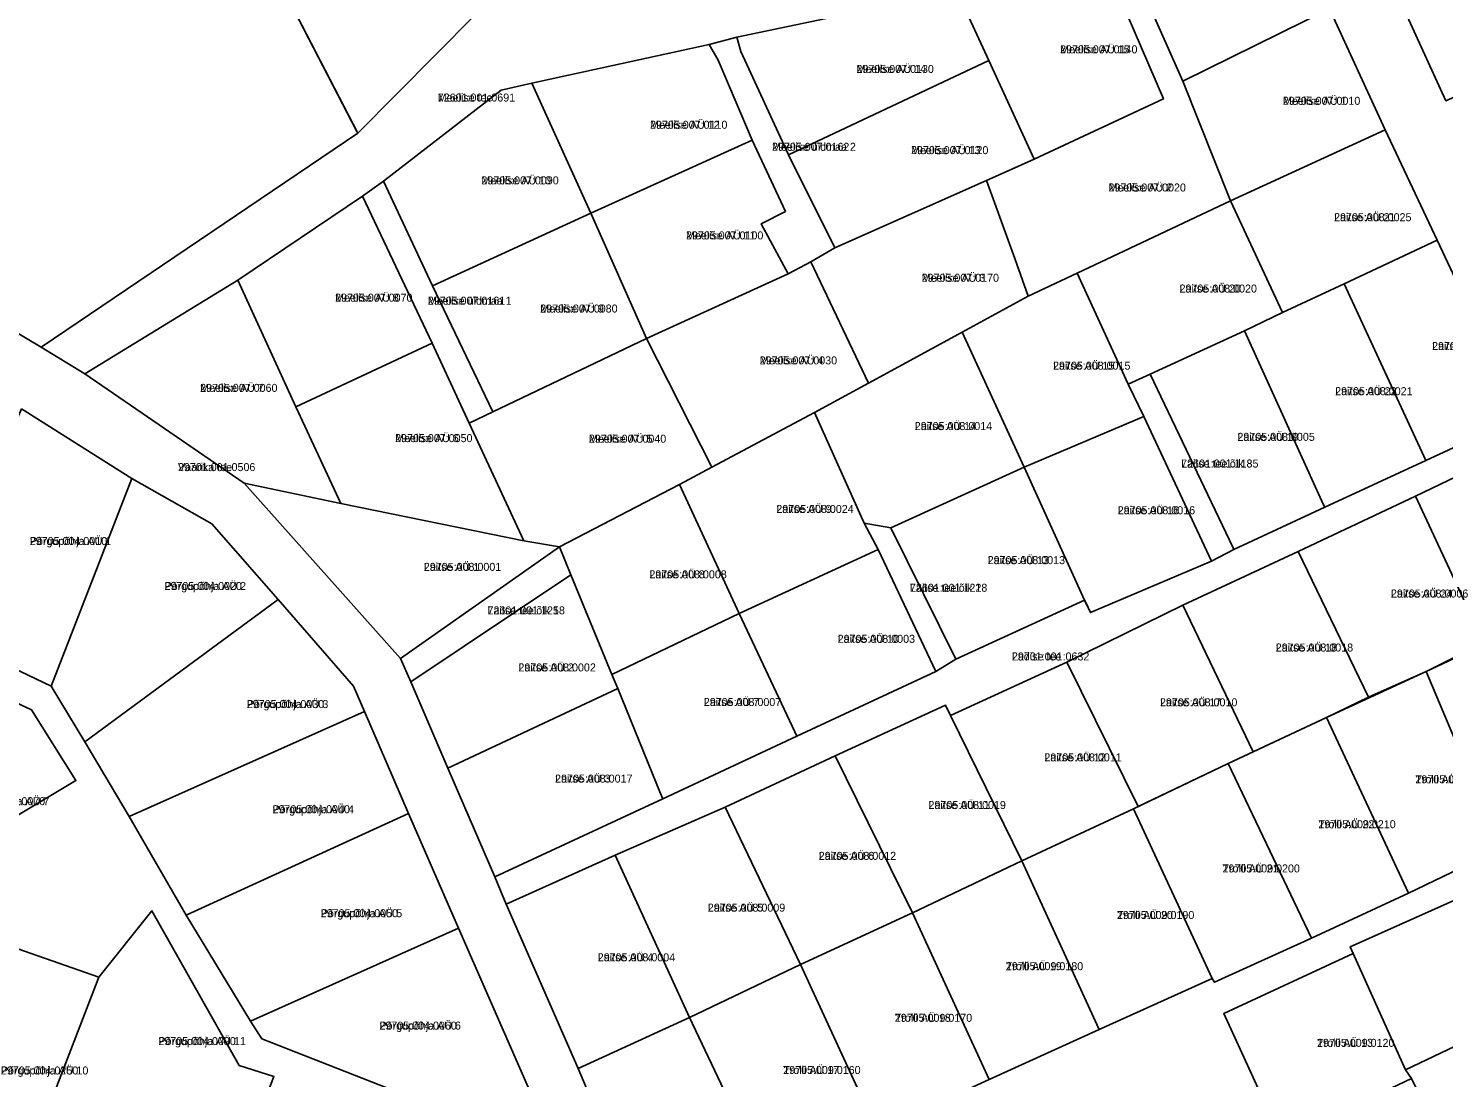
# Model space of a CAD drawing. Extents: x 504287 to 537970, y 6539941 to 6586214.
# Drawn here: x 519008.5 to 519273.8, y 6563004.5 to 6563201.2 of the extents above; entities that cross this region are included whole.
import ezdxf

# ---------------------------------------------------------------- set-up
doc = ezdxf.new("R2010")
doc.units = 0
for name, color, linetype in [('L_AADRESS', 7, 'Continuous'), ('PIIR', 7, 'Continuous'), ('TUNNUS', 7, 'Continuous')]:
    doc.layers.add(name, color=color, linetype=linetype)

msp = doc.modelspace()

# ---------------------------------------------------------------- linework, layer by layer
at = {"layer": 'PIIR'}
for points in [[(519053.34, 6563236.21), (519046.68, 6563227.13), (519070.28, 6563181.56), (519010.92, 6563141.43), (518931.33, 6563188.8), (519001.41, 6563278.34)], [(519236.2, 6563238.48), (519243.47, 6563223.81), (519238.26, 6563225.44), (519213.24, 6563217.67), (519209.13, 6563216.28), (519182.57, 6563208.19), (519141.33, 6563199.52), (519136.15, 6563198.16), (519102.94, 6563190.91), (519097.15, 6563189.57), (519075.1, 6563172.56), (519071.2, 6563169.74), (519047.83, 6563153.98), (519019.15, 6563136.44), (519010.92, 6563141.43), (519070.28, 6563181.56), (519092.24, 6563203.65), (519125.45, 6563208.08), (519151.08, 6563213.3), (519170.59, 6563217.51), (519190.06, 6563221.91), (519216.47, 6563228.93)], [(519070.28, 6563181.56), (519070.12, 6563181.87), (519046.68, 6563227.13), (519053.32, 6563236.18), (519074.71, 6563218.2), (519092.24, 6563203.65)], [(519293.15, 6563234.92), (519298.22, 6563198.28), (519274.24, 6563187.6), (519254.72, 6563230.35)], [(519213.24, 6563217.67), (519238.26, 6563225.44), (519243.47, 6563223.81), (519252.43, 6563204.86), (519224.92, 6563191.31)], [(519195.93, 6563150.95), (519193.44, 6563158.03), (519188.13, 6563172.69), (519197.09, 6563176.65), (519221.29, 6563187.94), (519209.13, 6563216.28), (519213.24, 6563217.67), (519224.92, 6563191.31), (519233.88, 6563168.84), (519205.14, 6563155.29)], [(519188.58, 6563195.18), (519182.57, 6563208.19), (519209.13, 6563216.28), (519221.29, 6563187.94), (519197.09, 6563176.65)], [(519142.12, 6563196.85), (519141.33, 6563199.52), (519182.57, 6563208.19), (519188.58, 6563195.18), (519151.01, 6563177.45)], [(519224.92, 6563191.31), (519252.43, 6563204.86), (519262.87, 6563182.15), (519233.88, 6563168.84)], [(519102.94, 6563190.91), (519136.15, 6563198.16), (519137.86, 6563195.24), (519144.24, 6563180.2), (519113.96, 6563166.55)], [(519145.9, 6563164.52), (519150.45, 6563166.86), (519144.24, 6563180.2), (519137.86, 6563195.24), (519136.15, 6563198.16), (519141.33, 6563199.52), (519142.12, 6563196.85), (519151.01, 6563177.45), (519159.7, 6563160.01), (519155.21, 6563157.43), (519150.94, 6563155.15)], [(519151.01, 6563177.45), (519188.58, 6563195.18), (519197.09, 6563176.65), (519188.13, 6563172.69), (519159.7, 6563160.01)], [(519075.1, 6563172.56), (519097.15, 6563189.57), (519102.94, 6563190.91), (519113.96, 6563166.55), (519084.3, 6563152.94)], [(519113.96, 6563166.55), (519144.24, 6563180.2), (519150.45, 6563166.86), (519145.9, 6563164.52), (519150.94, 6563155.15), (519124.44, 6563143.05)], [(519233.88, 6563168.84), (519262.87, 6563182.15), (519272.6, 6563161.46), (519255.16, 6563153.31), (519243.6, 6563147.91)], [(519075.1, 6563172.56), (519084.3, 6563152.94), (519095.63, 6563129.27), (519091.18, 6563127.15), (519084.26, 6563142.14), (519071.2, 6563169.74)], [(519155.21, 6563157.43), (519159.7, 6563160.01), (519188.13, 6563172.69), (519193.44, 6563158.03), (519195.93, 6563150.95), (519183.57, 6563144.21), (519166.03, 6563134.66)], [(519047.83, 6563153.98), (519071.2, 6563169.74), (519084.26, 6563142.14), (519058.69, 6563130.21)], [(519084.3, 6563152.94), (519113.96, 6563166.55), (519124.44, 6563143.05), (519095.63, 6563129.27)], [(519233.88, 6563168.84), (519243.6, 6563147.91), (519236.49, 6563144.51), (519218.8, 6563136.34), (519214.7, 6563134.49), (519205.14, 6563155.29)], [(519272.6, 6563161.46), (519288.16, 6563128.39), (519270.5, 6563120.2), (519255.16, 6563153.31)], [(519124.44, 6563143.05), (519150.94, 6563155.15), (519155.21, 6563157.43), (519166.03, 6563134.66), (519155.93, 6563129.16), (519136.66, 6563118.94)], [(519047.83, 6563153.98), (519058.69, 6563130.21), (519067.13, 6563112.11), (519049.02, 6563115.92), (519019.15, 6563136.44)], [(519195.93, 6563150.95), (519205.14, 6563155.29), (519214.7, 6563134.49), (519217.65, 6563128.44), (519195.17, 6563118.94), (519183.57, 6563144.21)], [(519236.49, 6563144.51), (519243.6, 6563147.91), (519255.16, 6563153.31), (519270.5, 6563120.2), (519251.54, 6563111.41), (519251.32, 6563111.88)], [(519101.43, 6563105.11), (519091.18, 6563127.15), (519095.63, 6563129.27), (519124.44, 6563143.05), (519136.66, 6563118.94), (519130.61, 6563115.68), (519108.1, 6563103.97)], [(519183.57, 6563144.21), (519195.17, 6563118.94), (519170.2, 6563107.54), (519165.23, 6563108.46), (519155.93, 6563129.16), (519166.03, 6563134.66)], [(519218.8, 6563136.34), (519236.49, 6563144.51), (519251.32, 6563111.88), (519251.54, 6563111.41), (519234.52, 6563103.51), (519234.39, 6563103.78)], [(519058.69, 6563130.21), (519084.26, 6563142.14), (519091.18, 6563127.15), (519101.43, 6563105.11), (519067.13, 6563112.11)], [(519218.8, 6563136.34), (519234.39, 6563103.78), (519234.52, 6563103.51), (519230.31, 6563101.3), (519217.65, 6563128.44), (519214.7, 6563134.49)], [(519007.26, 6563129.84), (519027.97, 6563116.81), (519012.79, 6563077.89), (518989.65, 6563088.92)], [(519130.61, 6563115.68), (519136.66, 6563118.94), (519155.93, 6563129.16), (519165.23, 6563108.46), (519167.85, 6563103.51), (519141.8, 6563091.51)], [(519096, 6563042.14), (519127.46, 6563056.78), (519152.61, 6563068.49), (519178.63, 6563080.61), (519182.36, 6563082.92), (519206.52, 6563094.02), (519207.64, 6563091.66), (519230.31, 6563101.3), (519234.52, 6563103.51), (519251.54, 6563111.41), (519270.5, 6563120.2), (519288.16, 6563128.39), (519290.29, 6563123.9), (519268.58, 6563113.51), (519246.55, 6563103.14), (519224.95, 6563093.03), (519203.18, 6563082.38), (519181.39, 6563072.35), (519180.43, 6563074.34), (519159.78, 6563064.8), (519139.13, 6563055.2), (519118.54, 6563046.17), (519098.11, 6563037)], [(519217.65, 6563128.44), (519230.31, 6563101.3), (519207.64, 6563091.66), (519206.79, 6563093.44), (519206.52, 6563094.02), (519195.17, 6563118.94)], [(519268.58, 6563113.51), (519290.29, 6563123.9), (519303.36, 6563096.05), (519281.35, 6563085.98)], [(519195.17, 6563118.94), (519206.52, 6563094.02), (519182.36, 6563082.92), (519170.2, 6563107.54)], [(519012.79, 6563077.89), (519027.97, 6563116.81), (519042.93, 6563108.32), (519055.34, 6563094.11), (519019.11, 6563067.44)], [(519049.02, 6563115.92), (519067.13, 6563112.11), (519101.43, 6563105.11), (519108.1, 6563103.97), (519078.28, 6563083.05)], [(519108.1, 6563103.97), (519130.61, 6563115.68), (519141.8, 6563091.51), (519117.92, 6563080.05), (519110.25, 6563098.77)], [(519268.58, 6563113.51), (519281.35, 6563085.98), (519270.53, 6563080.6), (519259.77, 6563075.79), (519246.55, 6563103.14)], [(519182.36, 6563082.92), (519178.63, 6563080.61), (519167.85, 6563103.51), (519165.23, 6563108.46), (519170.2, 6563107.54)], [(519110.25, 6563098.77), (519080.25, 6563078.7), (519078.28, 6563083.05), (519108.1, 6563103.97)], [(519141.8, 6563091.51), (519167.85, 6563103.51), (519178.63, 6563080.61), (519152.61, 6563068.49), (519152.21, 6563069.33)], [(519246.55, 6563103.14), (519259.77, 6563075.79), (519251.86, 6563071.99), (519238.14, 6563065.59), (519224.95, 6563093.03)], [(519080.25, 6563078.7), (519110.25, 6563098.77), (519117.92, 6563080.05), (519119.02, 6563077.46), (519087.16, 6563062.51)], [(519270.53, 6563080.6), (519303.36, 6563096.05), (519311.01, 6563079.31), (519277.56, 6563063.99)], [(519019.11, 6563067.44), (519055.34, 6563094.11), (519069.5, 6563077.89), (519071.55, 6563073.14), (519027.43, 6563053.43)], [(519224.95, 6563093.03), (519238.14, 6563065.59), (519233.43, 6563063.39), (519216.59, 6563055.31), (519203.18, 6563082.38)], [(519117.92, 6563080.05), (519141.8, 6563091.51), (519152.21, 6563069.33), (519152.61, 6563068.49), (519127.46, 6563056.78), (519127.05, 6563057.78), (519119.02, 6563077.46)], [(518987.82, 6563083.36), (519009.13, 6563073.43), (519017.47, 6563060.18), (519005.79, 6563053.18), (519001.51, 6563030.36), (518976.92, 6563040.6)], [(519181.39, 6563072.35), (519203.18, 6563082.38), (519216.59, 6563055.31), (519215.69, 6563054.88), (519194.75, 6563045.14)], [(519251.86, 6563071.99), (519270.53, 6563080.6), (519277.56, 6563063.99), (519285.2, 6563047.67), (519267.25, 6563039.05)], [(519087.16, 6563062.51), (519119.02, 6563077.46), (519127.05, 6563057.78), (519127.46, 6563056.78), (519096, 6563042.14)], [(519180.43, 6563074.34), (519181.39, 6563072.35), (519194.75, 6563045.14), (519174.27, 6563035.4), (519159.78, 6563064.8)], [(519027.43, 6563053.43), (519071.55, 6563073.14), (519079.79, 6563054.03), (519038.13, 6563034.98)], [(519233.43, 6563063.39), (519251.86, 6563071.99), (519267.25, 6563039.05), (519249.06, 6563030.62)], [(519139.13, 6563055.2), (519159.78, 6563064.8), (519174.27, 6563035.4), (519153.28, 6563025.68)], [(519230.44, 6563023.1), (519215.69, 6563054.88), (519233.43, 6563063.39), (519249.06, 6563030.62), (519230.89, 6563022.37)], [(519139.13, 6563055.2), (519153.28, 6563025.68), (519132.45, 6563015.78), (519118.54, 6563046.17)], [(519194.75, 6563045.14), (519215.69, 6563054.88), (519230.44, 6563023.1), (519209.25, 6563013.5)], [(519038.13, 6563034.98), (519079.79, 6563054.03), (519089.19, 6563032.5), (519050.19, 6563015.1)], [(519098.11, 6563037), (519118.54, 6563046.17), (519132.45, 6563015.78), (519111.61, 6563006.2)], [(519174.27, 6563035.4), (519194.75, 6563045.14), (519209.25, 6563013.5), (519188.62, 6563004.14)], [(519256.88, 6563027.76), (519256.32, 6563029.03), (519283.83, 6563041.33), (519294.48, 6563019.19), (519266.68, 6563005.97)], [(519021.76, 6563023.32), (519031.71, 6563035.77), (519048.05, 6563006.78), (519054.56, 6563004.69), (519046.04, 6562982.44), (519011.28, 6562996.06)], [(519153.28, 6563025.68), (519174.27, 6563035.4), (519188.62, 6563004.14), (519167.63, 6562994.53)], [(519050.19, 6563015.1), (519089.19, 6563032.5), (519103.52, 6562999.7), (519103.63, 6562997.17), (519096.3, 6562994.5), (519052.31, 6563011.78)], [(519001.51, 6563030.36), (519021.76, 6563023.32), (519011.28, 6562996.06), (519005.08, 6562979.84), (518985.05, 6562987.42)], [(519132.45, 6563015.78), (519153.28, 6563025.68), (519167.63, 6562994.53), (519147.16, 6562984.86)], [(519232.61, 6563016.49), (519256.88, 6563027.76), (519266.68, 6563005.97), (519267.83, 6563004.34), (519243.47, 6562992.78)], [(519267.83, 6563004.34), (519266.68, 6563005.97), (519294.48, 6563019.19), (519295.89, 6563016.27), (519300.23, 6563018.09), (519306.55, 6563004.35), (519277.21, 6562985.01)], [(519111.61, 6563006.2), (519132.45, 6563015.78), (519147.16, 6562984.86), (519125.05, 6562974.36)]]:
    msp.add_lwpolyline(points, close=True, dxfattribs=at)
for points in [[(519254.72, 6563230.35), (519274.24, 6563187.6)], [(519288.16, 6563128.39), (519272.6, 6563161.46), (519262.87, 6563182.15), (519252.43, 6563204.86)], [(518931.33, 6563188.8), (519010.92, 6563141.43), (519019.15, 6563136.44), (519049.02, 6563115.92), (519078.28, 6563083.05), (519080.25, 6563078.7), (519087.16, 6563062.51), (519096, 6563042.14), (519098.11, 6563037), (519111.61, 6563006.2), (519125.05, 6562974.36)], [(519103.52, 6562999.7), (519089.19, 6563032.5), (519079.79, 6563054.03), (519071.55, 6563073.14), (519069.5, 6563077.89), (519055.34, 6563094.11), (519042.93, 6563108.32), (519027.97, 6563116.81), (519007.26, 6563129.84)], [(518989.65, 6563088.92), (519012.79, 6563077.89), (519019.11, 6563067.44), (519027.43, 6563053.43), (519038.13, 6563034.98), (519050.19, 6563015.1), (519052.31, 6563011.78), (519096.3, 6562994.5)], [(519005.79, 6563053.18), (519017.47, 6563060.18), (519009.13, 6563073.43), (518987.82, 6563083.36)], [(519283.83, 6563041.33), (519256.32, 6563029.03), (519256.88, 6563027.76), (519232.61, 6563016.49), (519243.47, 6562992.78), (519238.7, 6562990.76), (519215.28, 6562978.65), (519219.04, 6562968.38), (519214.9, 6562966.23), (519206.68, 6562984.48), (519198.6, 6563002.16), (519165.68, 6562987.42), (519146.31, 6562978.89), (519127.11, 6562969.74), (519125.05, 6562974.36), (519147.16, 6562984.86), (519167.63, 6562994.53), (519188.62, 6563004.14), (519209.25, 6563013.5), (519230.44, 6563023.1), (519230.89, 6563022.37), (519249.06, 6563030.62), (519267.25, 6563039.05), (519285.2, 6563047.67)], [(519005.08, 6562979.84), (519015.34, 6562964.24), (519035.67, 6562956.3), (519046.04, 6562982.44), (519054.56, 6563004.69), (519048.05, 6563006.78), (519031.71, 6563035.77), (519021.76, 6563023.32), (519001.51, 6563030.36)]]:
    msp.add_lwpolyline(points, dxfattribs=at)

# ---------------------------------------------------------------- texts
at = {"layer": 'L_AADRESS'}
for s, p in [('Meelise AÜ 15', (519201.93, 6563196.5)), ('Meelise AÜ 14', (519163.77, 6563192.82)), ('Meelise tee', (519085.28, 6563187.46)), ('Meelise AÜ 1', (519243.7, 6563186.85)), ('Meelise AÜ 12', (519125.07, 6563182.36)), ('Meelise üldmaa 2', (519147.93, 6563178.23)), ('Meelise AÜ 13', (519173.99, 6563177.6)), ('Meelise AÜ 10', (519093.46, 6563171.93)), ('Meelise AÜ 2', (519211.01, 6563170.6)), ('Laitse AÜ 21', (519253.29, 6563165.03)), ('Meelise AÜ 11', (519131.81, 6563161.62)), ('Meelise AÜ 3', (519175.98, 6563153.68)), ('Laitse AÜ 20', (519224.33, 6563151.66)), ('Meelise AÜ 8', (519066.04, 6563149.95)), ('Meelise üldmaa 1', (519083.42, 6563149.38)), ('Meelise AÜ 9', (519104.49, 6563147.91)), ('Laitse AÜ 23', (519271.66, 6563140.88)), ('Meelise AÜ 4', (519145.63, 6563138.19)), ('Laitse AÜ 15', (519200.61, 6563137.2)), ('Meelise AÜ 7', (519040.74, 6563133.04)), ('Laitse AÜ 22', (519253.5, 6563132.42)), ('Laitse AÜ 14', (519174.7, 6563125.88)), ('Meelise AÜ 6', (519077.29, 6563123.62)), ('Meelise AÜ 5', (519113.61, 6563123.51)), ('Laitse AÜ 19', (519235.17, 6563123.86)), ('Vaarika tee', (519036.59, 6563118.19)), ('Laitse teelõik 3', (519224.61, 6563118.86)), ('Laitse AÜ 9', (519148.74, 6563110.34)), ('Laitse AÜ 16', (519212.74, 6563110.1)), ('Põrgupõhja AÜ 1', (519008.81, 6563104.33)), ('Laitse AÜ 1', (519082.68, 6563099.49)), ('Laitse AÜ 13', (519188.36, 6563100.75)), ('Põrgupõhja AÜ 2', (519034.07, 6563095.9)), ('Laitse AÜ 8', (519124.95, 6563098.08)), ('Laitse teelõik 2', (519173.79, 6563095.57)), ('Laitse AÜ 24', (519263.95, 6563094.49)), ('Laitse teelõik 1', (519094.61, 6563091.33)), ('Laitse AÜ 10', (519160.24, 6563086)), ('Ladise tee', (519192.91, 6563082.7)), ('Laitse AÜ 18', (519242.36, 6563084.37)), ('Laitse AÜ 2', (519100.41, 6563080.64)), ('Põrgupõhja AÜ 3', (519049.49, 6563073.77)), ('Laitse AÜ 7', (519135.16, 6563074.15)), ('Laitse AÜ 17', (519220.66, 6563074.1)), ('Laitse AÜ 12', (519198.99, 6563063.78)), ('Laitse AÜ 3', (519107.28, 6563059.8)), ('Trolli AÜ 23', (519268.53, 6563059.67)), ('Põrgupõhja AÜ 7', (518997.2, 6563055.57)), ('Põrgupõhja AÜ 4', (519054.31, 6563054.06)), ('Laitse AÜ 11', (519177.27, 6563054.85)), ('Trolli AÜ 22', (519250.34, 6563051.25)), ('Laitse AÜ 6', (519156.7, 6563045.32)), ('Trolli AÜ 21', (519232.38, 6563042.96)), ('Põrgupõhja AÜ 5', (519063.34, 6563034.57)), ('Laitse AÜ 5', (519135.91, 6563035.61)), ('Trolli AÜ 20', (519212.59, 6563034.23)), ('Laitse AÜ 4', (519115.28, 6563026.3)), ('Trolli AÜ 19', (519191.76, 6563024.64)), ('Põrgupõhja AÜ 6', (519074.35, 6563013.5)), ('Trolli AÜ 18', (519170.95, 6563014.96)), ('Põrgupõhja AÜ 11', (519032.92, 6563010.6)), ('Trolli AÜ 13', (519250.1, 6563010.27)), ('Põrgupõhja AÜ 10', (519003.4, 6563005.09)), ('Trolli AÜ 17', (519150.04, 6563005.18))]:
    msp.add_text(s, height=1.5, dxfattribs=at).set_placement(p)
at = {"layer": 'TUNNUS'}
for s, p in [('29705:007:0140', (519201.93, 6563196.5)), ('29705:007:0130', (519163.77, 6563192.82)), ('72601:001:0691', (519085.28, 6563187.46)), ('29705:007:0010', (519243.7, 6563186.85)), ('29705:007:0110', (519125.07, 6563182.36)), ('29705:007:0162', (519147.93, 6563178.23)), ('29705:007:0120', (519173.99, 6563177.6)), ('29705:007:0090', (519093.46, 6563171.93)), ('29705:007:0020', (519211.01, 6563170.6)), ('29705:008:0025', (519253.29, 6563165.03)), ('29705:007:0100', (519131.81, 6563161.62)), ('29705:007:0170', (519175.98, 6563153.68)), ('29705:008:0020', (519224.33, 6563151.66)), ('29705:007:0070', (519066.04, 6563149.95)), ('29705:007:0161', (519083.42, 6563149.38)), ('29705:007:0080', (519104.49, 6563147.91)), ('29705:008:0022', (519271.66, 6563140.88)), ('29705:007:0030', (519145.63, 6563138.19)), ('29705:008:0015', (519200.61, 6563137.2)), ('29705:007:0060', (519040.74, 6563133.04)), ('29705:008:0021', (519253.5, 6563132.42)), ('29705:008:0014', (519174.7, 6563125.88)), ('29705:007:0050', (519077.29, 6563123.62)), ('29705:007:0040', (519113.61, 6563123.51)), ('29705:008:0005', (519235.17, 6563123.86)), ('29701:001:0506', (519036.59, 6563118.19)), ('72601:001:1185', (519224.61, 6563118.86)), ('29705:008:0024', (519148.74, 6563110.34)), ('29705:008:0016', (519212.74, 6563110.1)), ('29705:004:0010', (519008.81, 6563104.33)), ('29705:008:0001', (519082.68, 6563099.49)), ('29705:008:0013', (519188.36, 6563100.75)), ('29705:004:0020', (519034.07, 6563095.9)), ('29705:008:0008', (519124.95, 6563098.08)), ('72601:001:1218', (519173.79, 6563095.57)), ('29705:008:0006', (519263.95, 6563094.49)), ('72601:001:1258', (519094.61, 6563091.33)), ('29705:008:0003', (519160.24, 6563086)), ('29701:001:0632', (519192.91, 6563082.7)), ('29705:008:0018', (519242.36, 6563084.37)), ('29705:008:0002', (519100.41, 6563080.64)), ('29705:004:0030', (519049.49, 6563073.77)), ('29705:008:0007', (519135.16, 6563074.15)), ('29705:008:0010', (519220.66, 6563074.1)), ('29705:008:0011', (519198.99, 6563063.78)), ('29705:008:0017', (519107.28, 6563059.8)), ('29705:009:0220', (519268.53, 6563059.67)), ('29705:004:0070', (518997.2, 6563055.57)), ('29705:004:0040', (519054.31, 6563054.06)), ('29705:008:0019', (519177.27, 6563054.85)), ('29705:009:0210', (519250.34, 6563051.25)), ('29705:008:0012', (519156.7, 6563045.32)), ('29705:009:0200', (519232.38, 6563042.96)), ('29705:008:0009', (519135.91, 6563035.61)), ('29705:004:0050', (519063.34, 6563034.57)), ('29705:009:0190', (519212.59, 6563034.23)), ('29705:008:0004', (519115.28, 6563026.3)), ('29705:009:0180', (519191.76, 6563024.64)), ('29705:009:0170', (519170.95, 6563014.96)), ('29705:004:0060', (519074.35, 6563013.5)), ('29705:004:0090', (519032.92, 6563010.6)), ('29705:009:0120', (519250.1, 6563010.27)), ('29705:004:0250', (519003.4, 6563005.09)), ('29705:009:0160', (519150.04, 6563005.18))]:
    msp.add_text(s, height=1.5, dxfattribs=at).set_placement(p)

doc.saveas('drawing.dxf')
